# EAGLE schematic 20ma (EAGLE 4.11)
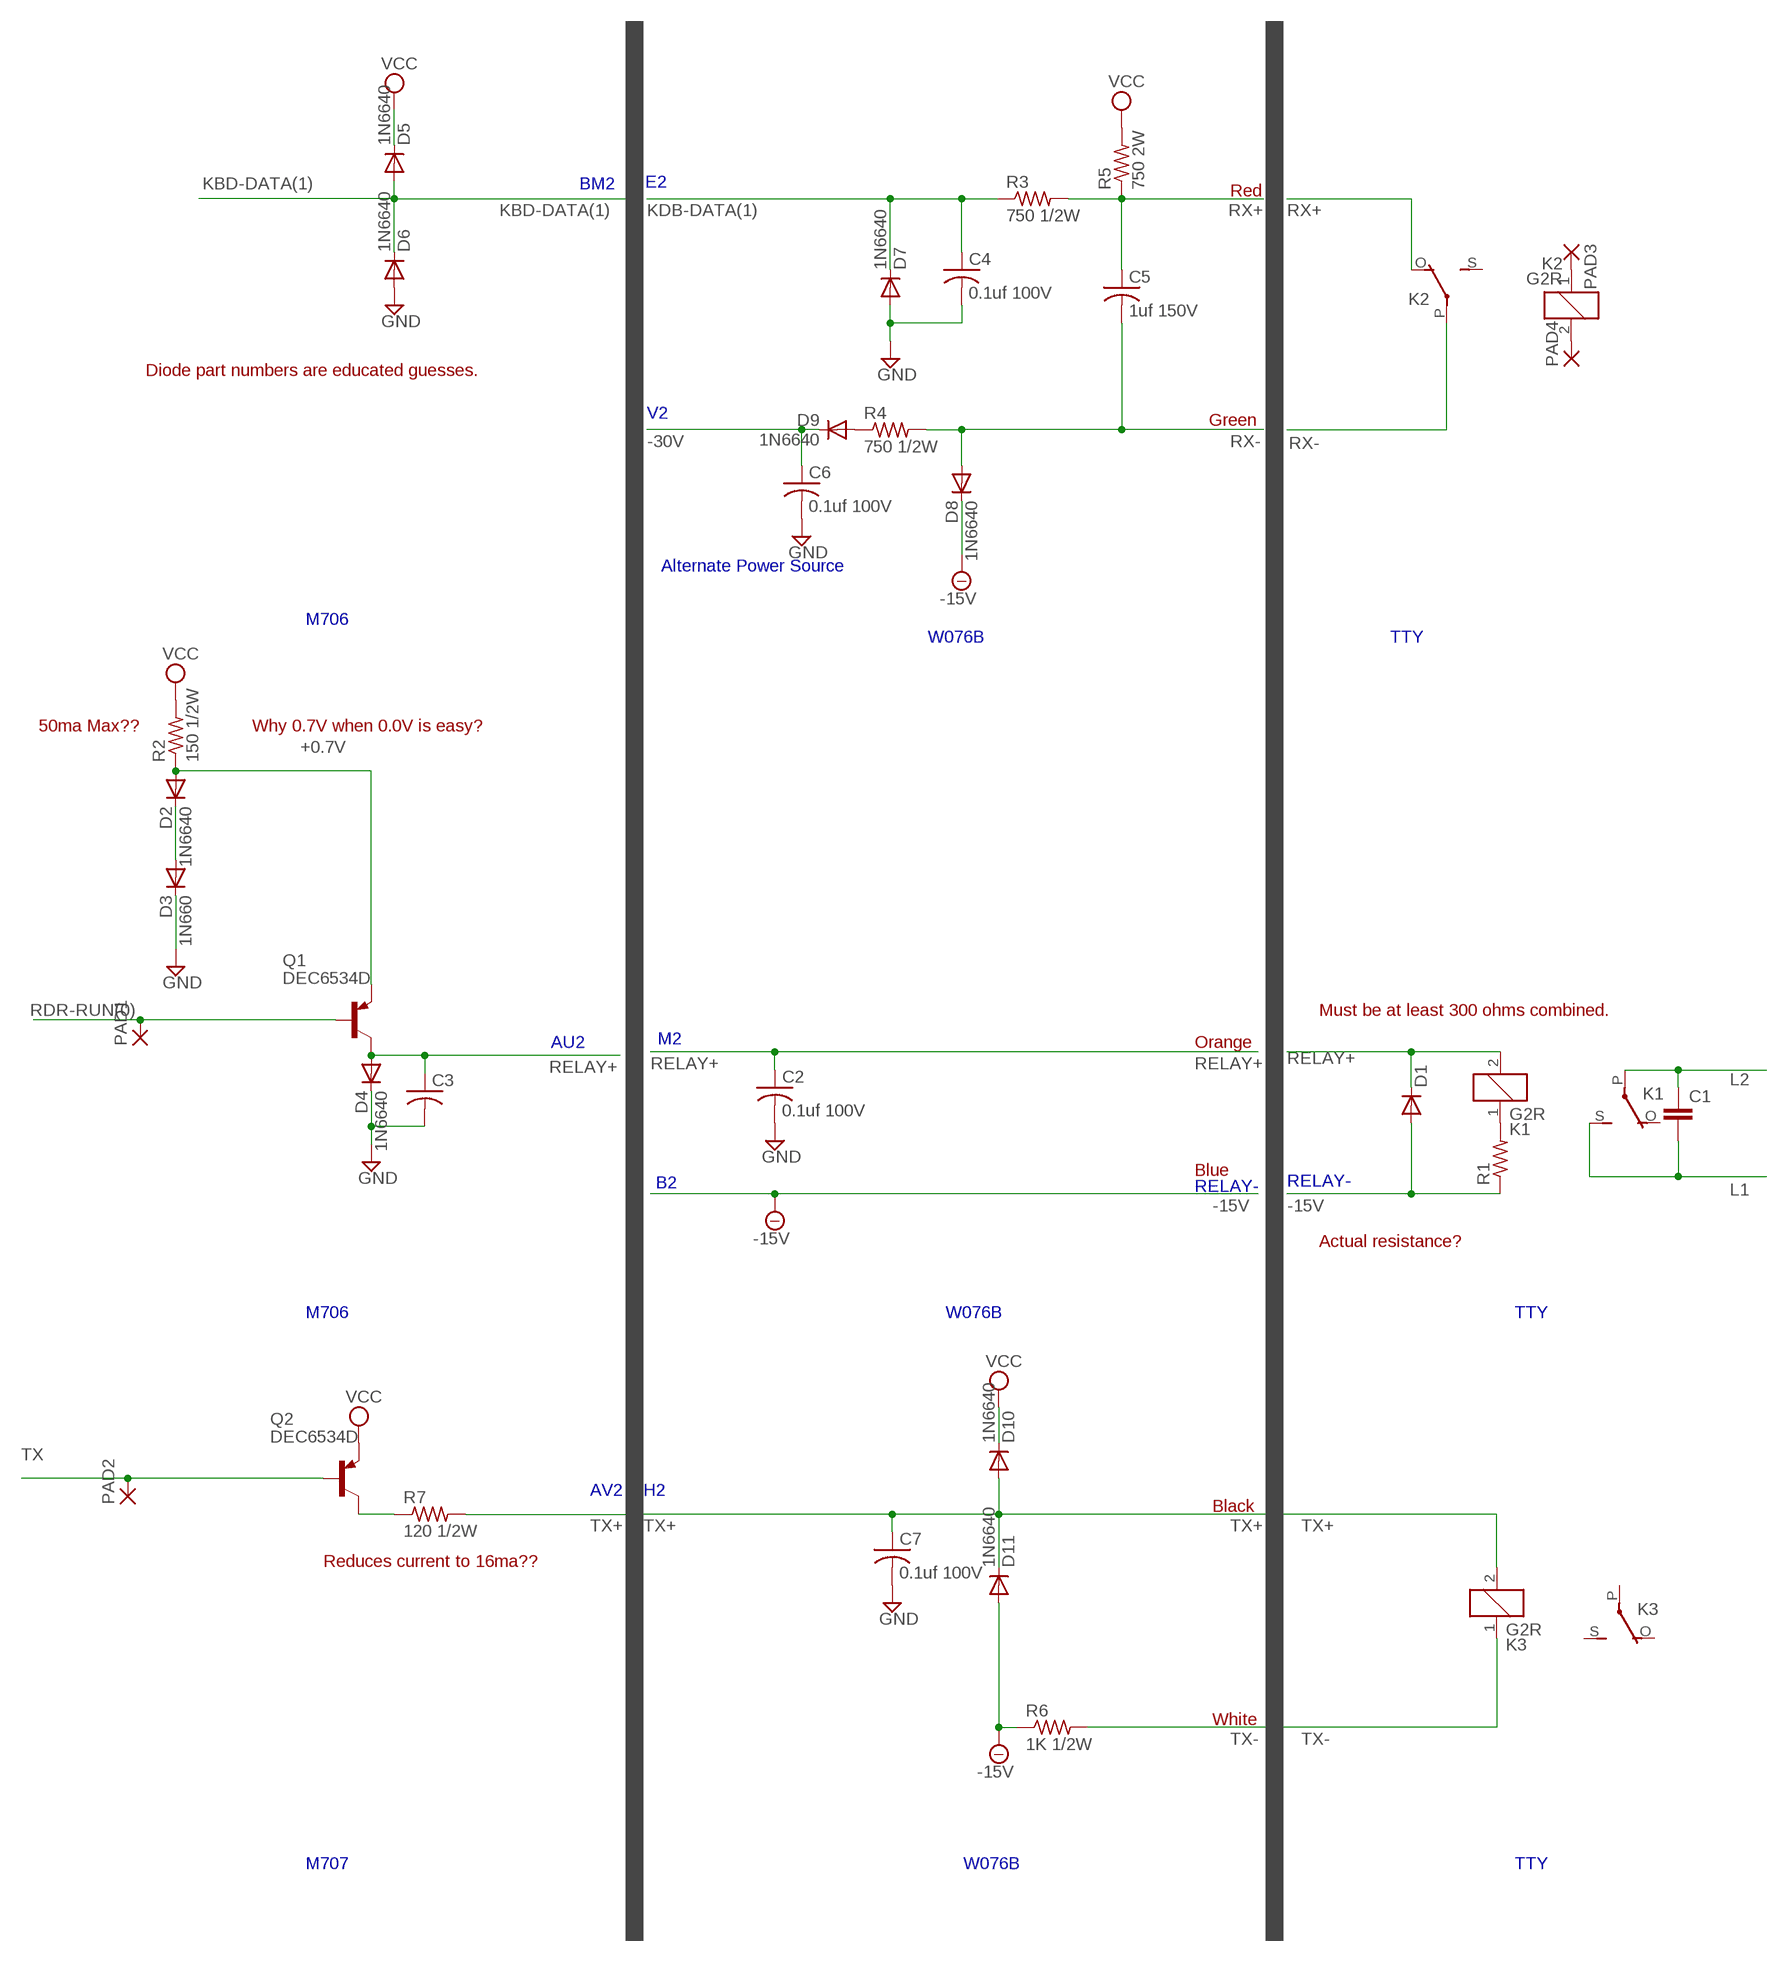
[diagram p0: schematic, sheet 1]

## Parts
C1  C22/10  [C22.5B10]
C2  0.1uf 100V  C-US025-025X050  [C025-025X050]
C3  C-US025-025X050  [C025-025X050]
C4  0.1uf 100V  C-US025-025X050  [C025-025X050]
C5  1uf 150V  C-US075-063X106  [C075-063X106]
C6  0.1uf 100V  C-US025-025X050  [C025-025X050]
C7  0.1uf 100V  C-US025-025X050  [C025-025X050]
D1  1N4004  [DO41-10]
D2  1N6640  1N4004  [DO41-10]
D3  1N660  1N4004  [DO41-10]
D4  1N6640  1N4004  [DO41-10]
D5  1N6640  1N4004  [DO41-10]
D6  1N6640  1N4004  [DO41-10]
D7  1N6640  1N4004  [DO41-10]
D8  1N6640  1N4004  [DO41-10]
D9  1N6640  1N4004  [DO41-10]
D10  1N6640  1N4004  [DO41-10]
D11  1N6640  1N4004  [DO41-10]
K1  G2R  [G2R]
K2  G2R  [G2R]
K3  G2R  [G2R]
PAD1  1,6/0,8  [1,6/0,8]
PAD2  1,6/0,8  [1,6/0,8]
PAD3  1,6/0,8  [1,6/0,8]
PAD4  1,6/0,8  [1,6/0,8]
Q1  DEC6534D  2N3906  [TO92]
Q2  DEC6534D  2N3906  [TO92]
R1  R-US_0309/12  [0309/12]
R2  150 1/2W  R-US_0207/10  [0207/10]
R3  750 1/2W  R-US_0309/12  [0309/12]
R4  750 1/2W  R-US_0309/12  [0309/12]
R5  750 2W  R-US_0309/12  [0309/12]
R6  1K 1/2W  R-US_0309/12  [0309/12]
R7  120 1/2W  R-US_0309/12  [0309/12]

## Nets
+0.7V: D2.A Q1.3(E) R2.1
-15V: D1.A D8.C D11.A R1.1 R6.1
-30V: C6.1 D9.C
GND: C2.2 C3.2 C4.2 C6.2 C7.2 D3.C D4.C D6.A D7.A
KBD-DATA(1): D5.A D6.C
KDB-DATA(1): C4.1 D7.C R3.1
L1: C1.2 K1.S(2:S)
L2: C1.1 K1.P(2:P)
N$1: K1.1 R1.2
N$2: D9.A R4.1
N$3: D2.C D3.A
N$4: Q2.1(C) R7.1
N$5: K2.1 PAD3.1(P)
N$6: K2.2 PAD4.1(P)
RDR-RUN(0): PAD1.1(P) Q1.2(B)
RELAY+: C2.1 C3.1 D1.C D4.A K1.2 Q1.1(C)
RX+: C5.1 K2.O(2:O) R3.2 R5.1
RX-: C5.2 D8.A K2.P(2:P) R4.2
TX: PAD2.1(P) Q2.2(B)
TX+: C7.1 D10.A D11.C K3.2 R7.2
TX-: K3.1 R6.2
VCC: D5.C D10.C Q2.3(E) R2.2 R5.2
Unconnected: K1.O(2:O) K2.S(2:S) K3.O(2:O) K3.P(2:P) K3.S(2:S)

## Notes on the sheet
- BM2 | E2
- Red
- Diode part numbers are educated guesses.
- V2
- Green
- Alternate Power Source
- M706
- W076B | TTY
- 50ma Max?? | Why 0.7V when 0.0V is easy?
- Must be at least 300 ohms combined.
- AU2 | M2 | Orange
- Blue
- B2 | RELAY-
- RELAY-
- Actual resistance?
- M706 | W076B | TTY
- AV2 | H2
- Black
- Reduces current to 16ma??
- White
- M707 | W076B | TTY

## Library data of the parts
C1 = capacitor-wima:C: CAPACITOR
C2-C7 = rcl:C-US: CAPACITOR, American symbol
D1-D11 = diode:1N4004: DIODE
K1-K3 = relay:G2R: RELAY 1 x switch, Omron
PAD1-PAD4 = wirepad:1,6/0,8: THROUGH-HOLE PAD
Q1 Q2 = transistor-pnp:2N3906: PNP Transistor
R1-R7 = rcl:R-US_: RESISTOR, American symbol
